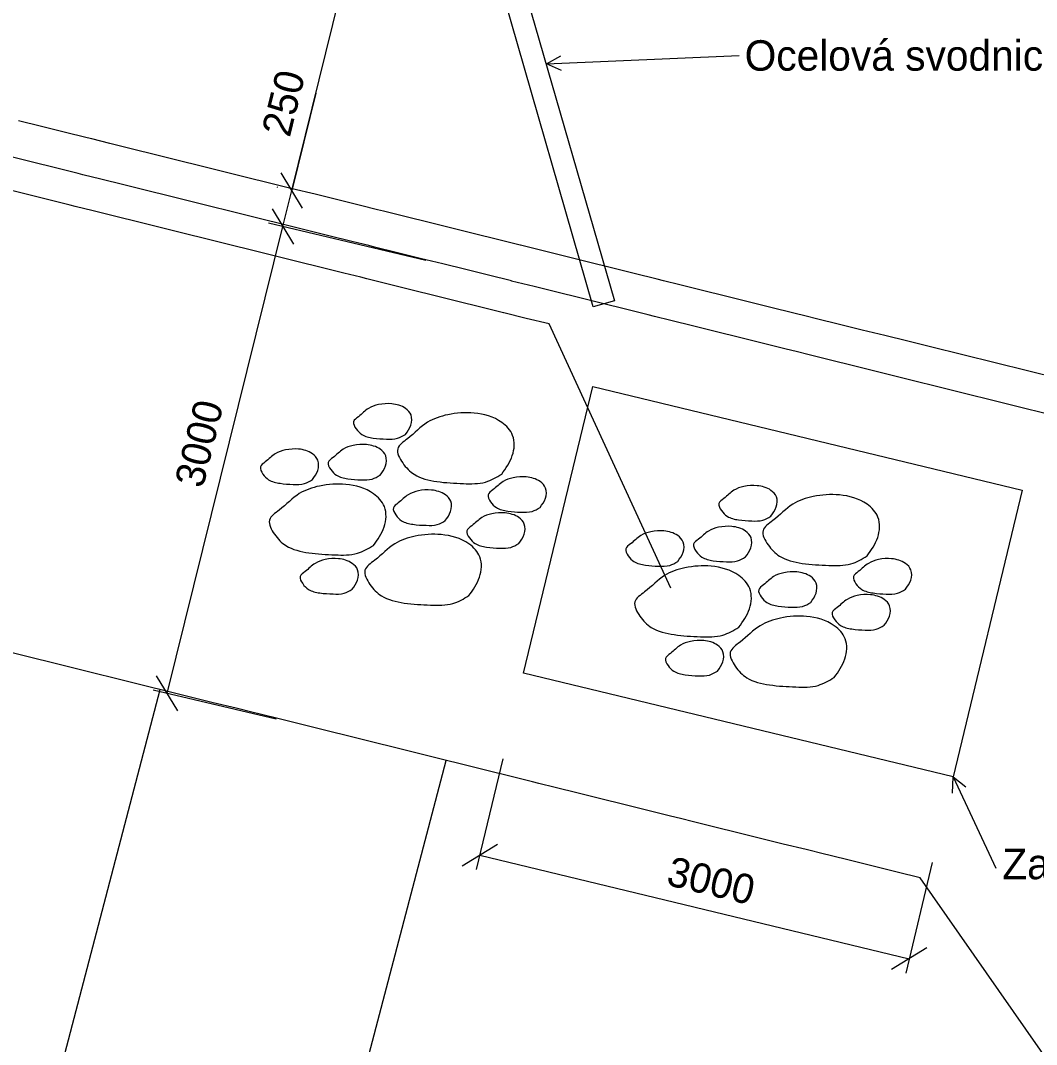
# Model space of a CAD drawing. Extents: x -577013.5 to -576971.5, y -1164310.3 to -1164280.6.
# Drawn here: x -577004.93 to -576998.03, y -1164300.03 to -1164293.08 of the extents above; entities that cross this region are included whole.
import ezdxf

# ---------------------------------------------------------------- set-up
doc = ezdxf.new("R2010")
doc.units = 0
for name, color, linetype in [('V_N1_detaily', 7, 'Continuous'), ('Vrstva 1', 7, 'Continuous'), ('Šrafy', 7, 'Continuous')]:
    doc.layers.add(name, color=color, linetype=linetype)

msp = doc.modelspace()

# ---------------------------------------------------------------- linework, layer by layer
for p, q in [((-577002.7891, -1164288.4094), (-577000.8944, -1164294.9817)), ((-577001.0385, -1164295.0232), (-577002.9332, -1164288.451)), ((-577003.0856, -1164294.2333), (-577001.7682, -1164288.9174)), ((-577002.9216, -1164293.5719), (-577003.0856, -1164294.2333)), ((-577004.7861, -1164293.7991), (-577004.941, -1164293.7607)), ((-577004.6313, -1164293.8375), (-577004.7861, -1164293.7991)), ((-577004.4764, -1164293.8758), (-577004.6313, -1164293.8375)), ((-577004.4445, -1164293.8837), (-577004.4764, -1164293.8758)), ((-577004.3216, -1164293.9142), (-577004.4445, -1164293.8837)), ((-577004.1667, -1164293.9526), (-577004.3216, -1164293.9142)), ((-577004.0118, -1164293.991), (-577004.1667, -1164293.9526)), ((-577003.857, -1164294.0293), (-577004.0118, -1164293.991)), ((-577004.8463, -1164294.0417), (-577005.0011, -1164294.0034)), ((-577004.6914, -1164294.0801), (-577004.8463, -1164294.0417)), ((-577003.7021, -1164294.0677), (-577003.857, -1164294.0293)), ((-577003.5473, -1164294.1061), (-577003.7021, -1164294.0677)), ((-577004.5365, -1164294.1185), (-577004.6914, -1164294.0801)), ((-577004.5046, -1164294.1264), (-577004.5365, -1164294.1185)), ((-577004.3817, -1164294.1569), (-577004.5046, -1164294.1264)), ((-577003.4738, -1164294.1243), (-577003.5473, -1164294.1061)), ((-577003.3924, -1164294.1445), (-577003.4738, -1164294.1243)), ((-577003.013, -1164294.3529), (-577003.1581, -1164294.1137)), ((-577003.013, -1164294.3529), (-577003.1581, -1164294.1137)), ((-577004.2268, -1164294.1952), (-577004.3817, -1164294.1569)), ((-577004.072, -1164294.2336), (-577004.2268, -1164294.1952)), ((-577003.2376, -1164294.1828), (-577003.3924, -1164294.1445)), ((-577003.0827, -1164294.2212), (-577003.2376, -1164294.1828)), ((-577004.8996, -1164294.2571), (-577005.0545, -1164294.2187)), ((-577004.7448, -1164294.2955), (-577004.8996, -1164294.2571)), ((-577003.9171, -1164294.272), (-577004.072, -1164294.2336)), ((-577003.7623, -1164294.3104), (-577003.9171, -1164294.272)), ((-577003.1879, -1164294.209), (-577003.1821, -1164294.2104)), ((-577003.1462, -1164294.4779), (-577003.0856, -1164294.2333)), ((-577002.9279, -1164294.2596), (-577003.0827, -1164294.2212)), ((-577002.773, -1164294.298), (-577002.9279, -1164294.2596)), ((-577004.5899, -1164294.3338), (-577004.7448, -1164294.2955)), ((-577004.558, -1164294.3418), (-577004.5899, -1164294.3338)), ((-577004.4351, -1164294.3722), (-577004.558, -1164294.3418)), ((-577003.6074, -1164294.3487), (-577003.7623, -1164294.3104)), ((-577002.6181, -1164294.3363), (-577002.773, -1164294.298)), ((-577002.5032, -1164294.3648), (-577002.6181, -1164294.3363)), ((-577004.2802, -1164294.4106), (-577004.4351, -1164294.3722)), ((-577004.1253, -1164294.449), (-577004.2802, -1164294.4106)), ((-577003.534, -1164294.3669), (-577003.6074, -1164294.3487)), ((-577003.4526, -1164294.3871), (-577003.534, -1164294.3669)), ((-577003.2977, -1164294.4255), (-577003.4526, -1164294.3871)), ((-577003.2187, -1164294.3583), (-577003.0736, -1164294.5975)), ((-577003.2187, -1164294.3583), (-577003.0736, -1164294.5975)), ((-577002.4633, -1164294.3747), (-577002.5032, -1164294.3648)), ((-577002.3084, -1164294.4131), (-577002.4633, -1164294.3747)), ((-577002.1536, -1164294.4515), (-577002.3084, -1164294.4131)), ((-577003.9705, -1164294.4873), (-577004.1253, -1164294.449)), ((-577003.9316, -1164297.6472), (-577003.1462, -1164294.4779)), ((-577003.1428, -1164294.4639), (-577003.2977, -1164294.4255)), ((-577002.1761, -1164294.7077), (-577003.2427, -1164294.455)), ((-577003.1845, -1164294.6327), (-577003.1462, -1164294.4779)), ((-577002.988, -1164294.5022), (-577003.1428, -1164294.4639)), ((-577001.9987, -1164294.4898), (-577002.1536, -1164294.4515)), ((-577003.8156, -1164294.5257), (-577003.9705, -1164294.4873)), ((-577003.6608, -1164294.5641), (-577003.8156, -1164294.5257)), ((-577002.8331, -1164294.5406), (-577002.988, -1164294.5022)), ((-577002.6783, -1164294.579), (-577002.8331, -1164294.5406)), ((-577001.8439, -1164294.5282), (-577001.9987, -1164294.4898)), ((-577001.689, -1164294.5666), (-577001.8439, -1164294.5282)), ((-577003.5873, -1164294.5823), (-577003.6608, -1164294.5641)), ((-577003.5059, -1164294.6025), (-577003.5873, -1164294.5823)), ((-577003.3511, -1164294.6408), (-577003.5059, -1164294.6025)), ((-577002.5633, -1164294.6075), (-577002.6783, -1164294.579)), ((-577002.5234, -1164294.6174), (-577002.5633, -1164294.6075)), ((-577002.3686, -1164294.6558), (-577002.5234, -1164294.6174)), ((-577001.5342, -1164294.605), (-577001.689, -1164294.5666)), ((-577001.5326, -1164294.6054), (-577001.5342, -1164294.605)), ((-577001.3793, -1164294.6433), (-577001.5326, -1164294.6054)), ((-577003.1962, -1164294.6792), (-577003.3511, -1164294.6408)), ((-577003.0414, -1164294.7176), (-577003.1962, -1164294.6792)), ((-577002.2137, -1164294.6941), (-577002.3686, -1164294.6558)), ((-577002.0589, -1164294.7325), (-577002.2137, -1164294.6941)), ((-577001.2244, -1164294.6817), (-577001.3793, -1164294.6433)), ((-577001.0696, -1164294.7201), (-577001.2244, -1164294.6817)), ((-577002.8865, -1164294.756), (-577003.0414, -1164294.7176)), ((-577002.7316, -1164294.7944), (-577002.8865, -1164294.756)), ((-577001.904, -1164294.7709), (-577002.0589, -1164294.7325)), ((-577000.9147, -1164294.7585), (-577001.0696, -1164294.7201)), ((-577000.7599, -1164294.7968), (-577000.9147, -1164294.7585)), ((-577002.6167, -1164294.8228), (-577002.7316, -1164294.7944)), ((-577002.5768, -1164294.8327), (-577002.6167, -1164294.8228)), ((-577002.4219, -1164294.8711), (-577002.5768, -1164294.8327)), ((-577001.7491, -1164294.8093), (-577001.904, -1164294.7709)), ((-577001.5943, -1164294.8476), (-577001.7491, -1164294.8093)), ((-577000.605, -1164294.8352), (-577000.7599, -1164294.7968)), ((-577002.2671, -1164294.9095), (-577002.4219, -1164294.8711)), ((-577001.5927, -1164294.848), (-577001.5943, -1164294.8476)), ((-577001.4394, -1164294.886), (-577001.5927, -1164294.848)), ((-577001.2846, -1164294.9244), (-577001.4394, -1164294.886)), ((-577000.5619, -1164294.8459), (-577000.605, -1164294.8352)), ((-577000.4502, -1164294.8736), (-577000.5619, -1164294.8459)), ((-577000.2953, -1164294.912), (-577000.4502, -1164294.8736)), ((-577002.1122, -1164294.9479), (-577002.2671, -1164294.9095)), ((-577001.9574, -1164294.9862), (-577002.1122, -1164294.9479)), ((-577001.1297, -1164294.9628), (-577001.2846, -1164294.9244)), ((-577000.9749, -1164295.0011), (-577001.1297, -1164294.9628)), ((-577000.1405, -1164294.9504), (-577000.2953, -1164294.912)), ((-576999.9856, -1164294.9887), (-577000.1405, -1164294.9504)), ((-577001.8025, -1164295.0246), (-577001.9574, -1164294.9862)), ((-577001.6477, -1164295.063), (-577001.8025, -1164295.0246)), ((-577000.8944, -1164294.9817), (-577001.0385, -1164295.0232)), ((-577000.82, -1164295.0395), (-577000.9749, -1164295.0011)), ((-577000.6652, -1164295.0779), (-577000.82, -1164295.0395)), ((-576999.8308, -1164295.0271), (-576999.9856, -1164294.9887)), ((-576999.6759, -1164295.0655), (-576999.8308, -1164295.0271)), ((-577001.6461, -1164295.0634), (-577001.6477, -1164295.063)), ((-577001.4928, -1164295.1014), (-577001.6461, -1164295.0634)), ((-577001.338, -1164295.1397), (-577001.4928, -1164295.1014)), ((-577000.6221, -1164295.0886), (-577000.6652, -1164295.0779)), ((-577000.5103, -1164295.1163), (-577000.6221, -1164295.0886)), ((-576999.5913, -1164295.0864), (-576999.6759, -1164295.0655)), ((-576999.521, -1164295.1039), (-576999.5913, -1164295.0864)), ((-576999.3662, -1164295.1422), (-576999.521, -1164295.1039)), ((-577000.5115, -1164296.9339), (-577001.338, -1164295.1397)), ((-577000.3555, -1164295.1546), (-577000.5103, -1164295.1163)), ((-577000.2006, -1164295.193), (-577000.3555, -1164295.1546)), ((-576999.2113, -1164295.1806), (-576999.3662, -1164295.1422)), ((-576999.0565, -1164295.219), (-576999.2113, -1164295.1806)), ((-577000.0457, -1164295.2314), (-577000.2006, -1164295.193)), ((-576999.8909, -1164295.2698), (-577000.0457, -1164295.2314)), ((-576998.9016, -1164295.2574), (-576999.0565, -1164295.219)), ((-576999.736, -1164295.3081), (-576999.8909, -1164295.2698)), ((-576999.6514, -1164295.3291), (-576999.736, -1164295.3081)), ((-576998.7468, -1164295.2957), (-576998.9016, -1164295.2574)), ((-576996.2548, -1164295.9082), (-576998.7468, -1164295.2957)), ((-576999.5812, -1164295.3465), (-576999.6514, -1164295.3291)), ((-576999.4263, -1164295.3849), (-576999.5812, -1164295.3465)), ((-576999.2715, -1164295.4233), (-576999.4263, -1164295.3849)), ((-576999.1166, -1164295.4616), (-576999.2715, -1164295.4233)), ((-576998.9618, -1164295.5), (-576999.1166, -1164295.4616)), ((-576996.3092, -1164296.1623), (-576998.9618, -1164295.5)), ((-577001.5108, -1164297.5093), (-577001.0418, -1164295.5651)), ((-577001.0418, -1164295.5651), (-576998.1255, -1164296.2686)), ((-576998.1255, -1164296.2686), (-576998.5945, -1164298.2128)), ((-577004.8575, -1164297.4033), (-577005.0123, -1164297.3649)), ((-577004.7026, -1164297.4417), (-577004.8575, -1164297.4033)), ((-577004.5478, -1164297.4801), (-577004.7026, -1164297.4417)), ((-577004.3929, -1164297.5185), (-577004.5478, -1164297.4801)), ((-577004.3195, -1164297.5367), (-577004.3929, -1164297.5185)), ((-577004.2381, -1164297.5568), (-577004.3195, -1164297.5367)), ((-577003.859, -1164297.7668), (-577004.0041, -1164297.5276)), ((-576998.5945, -1164298.2128), (-577001.5108, -1164297.5093)), ((-577004.0832, -1164297.5952), (-577004.2381, -1164297.5568)), ((-577003.9284, -1164297.6336), (-577004.0832, -1164297.5952)), ((-577003.1913, -1164297.8226), (-577004.0281, -1164297.6243)), ((-577003.7735, -1164297.672), (-577003.9284, -1164297.6336)), ((-577003.6186, -1164297.7103), (-577003.7735, -1164297.672)), ((-577003.4638, -1164297.7487), (-577003.6186, -1164297.7103)), ((-577003.3488, -1164297.7772), (-577003.4638, -1164297.7487)), ((-577003.3089, -1164297.7871), (-577003.3488, -1164297.7772)), ((-577003.1541, -1164297.8255), (-577003.3089, -1164297.7871)), ((-577002.9992, -1164297.8638), (-577003.1541, -1164297.8255)), ((-577002.8444, -1164297.9022), (-577002.9992, -1164297.8638)), ((-577002.6895, -1164297.9406), (-577002.8444, -1164297.9022)), ((-577002.5347, -1164297.979), (-577002.6895, -1164297.9406)), ((-577002.3798, -1164298.0173), (-577002.5347, -1164297.979)), ((-577002.3782, -1164298.0177), (-577002.3798, -1164298.0173)), ((-577002.2249, -1164298.0557), (-577002.3782, -1164298.0177)), ((-577002.0701, -1164298.0941), (-577002.2249, -1164298.0557)), ((-577001.9152, -1164298.1325), (-577002.0701, -1164298.0941)), ((-577001.6515, -1164298.0926), (-577001.8323, -1164298.842)), ((-577001.7604, -1164298.1708), (-577001.9152, -1164298.1325)), ((-577001.6055, -1164298.2092), (-577001.7604, -1164298.1708)), ((-577001.4507, -1164298.2476), (-577001.6055, -1164298.2092)), ((-577001.4076, -1164298.2583), (-577001.4507, -1164298.2476)), ((-577001.2958, -1164298.286), (-577001.4076, -1164298.2583)), ((-577001.141, -1164298.3243), (-577001.2958, -1164298.286)), ((-577000.9861, -1164298.3627), (-577001.141, -1164298.3243)), ((-577000.8312, -1164298.4011), (-577000.9861, -1164298.3627)), ((-577000.6764, -1164298.4395), (-577000.8312, -1164298.4011)), ((-577000.5215, -1164298.4778), (-577000.6764, -1164298.4395)), ((-577000.4369, -1164298.4988), (-577000.5215, -1164298.4778)), ((-577000.3667, -1164298.5162), (-577000.4369, -1164298.4988)), ((-577000.2118, -1164298.5546), (-577000.3667, -1164298.5162)), ((-577000.057, -1164298.593), (-577000.2118, -1164298.5546)), ((-576999.9021, -1164298.6314), (-577000.057, -1164298.593)), ((-576999.7473, -1164298.6697), (-576999.9021, -1164298.6314)), ((-577001.9295, -1164298.8185), (-577001.6882, -1164298.671)), ((-576999.5924, -1164298.7081), (-576999.7473, -1164298.6697)), ((-576999.4663, -1164298.7394), (-576999.5924, -1164298.7081)), ((-577001.8089, -1164298.7447), (-576998.8925, -1164299.4483)), ((-576999.4376, -1164298.7465), (-576999.4663, -1164298.7394)), ((-576999.2827, -1164298.7849), (-576999.4376, -1164298.7465)), ((-576999.1278, -1164298.8232), (-576999.2827, -1164298.7849)), ((-576998.973, -1164298.8616), (-576999.1278, -1164298.8232)), ((-576998.8181, -1164298.9), (-576998.973, -1164298.8616)), ((-576998.7352, -1164298.7961), (-576998.916, -1164299.5455)), ((-576996.082, -1164302.8053), (-576998.8181, -1164298.9)), ((-576998.7719, -1164299.3745), (-576999.0132, -1164299.522))]:
    msp.add_line(p, q)
at = {"layer": 'V_N1_detaily'}
for points in [[(-577002.313, -1164295.8889), (-577002.3676, -1164295.9157), (-577002.4429, -1164295.9211), (-577002.533, -1164295.914), (-577002.6101, -1164295.8897), (-577002.6491, -1164295.8509), (-577002.666, -1164295.803), (-577002.633, -1164295.7689), (-577002.5648, -1164295.7131), (-577002.496, -1164295.6873), (-577002.4068, -1164295.6818), (-577002.3127, -1164295.7134), (-577002.2759, -1164295.7574), (-577002.2768, -1164295.8262), (-577002.313, -1164295.8889)], [(-577001.6601, -1164296.1587), (-577001.7694, -1164296.2124), (-577001.9199, -1164296.2231), (-577002.1001, -1164296.209), (-577002.2543, -1164296.1603), (-577002.3323, -1164296.0828), (-577002.3662, -1164295.987), (-577002.3001, -1164295.9189), (-577002.1638, -1164295.8072), (-577002.0261, -1164295.7556), (-577001.8477, -1164295.7446), (-577001.6595, -1164295.8078), (-577001.5859, -1164295.8958), (-577001.5877, -1164296.0333), (-577001.6601, -1164296.1587)], [(-577002.9457, -1164296.1962), (-577003.0003, -1164296.223), (-577003.0756, -1164296.2284), (-577003.1657, -1164296.2213), (-577003.2428, -1164296.197), (-577003.2818, -1164296.1582), (-577003.2987, -1164296.1103), (-577003.2657, -1164296.0762), (-577003.1975, -1164296.0204), (-577003.1287, -1164295.9946), (-577003.0395, -1164295.9891), (-577002.9454, -1164296.0207), (-577002.9086, -1164296.0647), (-577002.9095, -1164296.1334), (-577002.9457, -1164296.1962)], [(-577002.4851, -1164296.1657), (-577002.5398, -1164296.1925), (-577002.615, -1164296.1979), (-577002.7051, -1164296.1908), (-577002.7822, -1164296.1665), (-577002.8212, -1164296.1277), (-577002.8382, -1164296.0798), (-577002.8051, -1164296.0457), (-577002.737, -1164295.9899), (-577002.6681, -1164295.9641), (-577002.5789, -1164295.9586), (-577002.4848, -1164295.9902), (-577002.448, -1164296.0342), (-577002.4489, -1164296.103), (-577002.4851, -1164296.1657)], [(-577002.5309, -1164296.6428), (-577002.6402, -1164296.6964), (-577002.7908, -1164296.7072), (-577002.9709, -1164296.6931), (-577003.1251, -1164296.6444), (-577003.2031, -1164296.5668), (-577003.237, -1164296.471), (-577003.1709, -1164296.4029), (-577003.0346, -1164296.2913), (-577002.8969, -1164296.2397), (-577002.7185, -1164296.2287), (-577002.5304, -1164296.2919), (-577002.4567, -1164296.3798), (-577002.4585, -1164296.5174), (-577002.5309, -1164296.6428)], [(-577001.3991, -1164296.385), (-577001.4537, -1164296.4118), (-577001.529, -1164296.4172), (-577001.6191, -1164296.4101), (-577001.6962, -1164296.3858), (-577001.7352, -1164296.347), (-577001.7521, -1164296.2991), (-577001.7191, -1164296.265), (-577001.6509, -1164296.2092), (-577001.5821, -1164296.1834), (-577001.4929, -1164296.1779), (-577001.3988, -1164296.2095), (-577001.362, -1164296.2535), (-577001.3629, -1164296.3223), (-577001.3991, -1164296.385)], [(-577002.0428, -1164296.4743), (-577002.0974, -1164296.5011), (-577002.1727, -1164296.5065), (-577002.2628, -1164296.4995), (-577002.3399, -1164296.4751), (-577002.3789, -1164296.4363), (-577002.3958, -1164296.3884), (-577002.3628, -1164296.3544), (-577002.2946, -1164296.2986), (-577002.2258, -1164296.2728), (-577002.1366, -1164296.2673), (-577002.0425, -1164296.2989), (-577002.0057, -1164296.3428), (-577002.0066, -1164296.4116), (-577002.0428, -1164296.4743)], [(-576999.8314, -1164296.4444), (-576999.8861, -1164296.4712), (-576999.9614, -1164296.4766), (-577000.0515, -1164296.4696), (-577000.1286, -1164296.4452), (-577000.1676, -1164296.4065), (-577000.1845, -1164296.3585), (-577000.1514, -1164296.3245), (-577000.0833, -1164296.2687), (-577000.0144, -1164296.2429), (-576999.9253, -1164296.2374), (-576999.8312, -1164296.269), (-576999.7944, -1164296.313), (-576999.7953, -1164296.3817), (-576999.8314, -1164296.4444)], [(-576999.1785, -1164296.7143), (-576999.2879, -1164296.7679), (-576999.4384, -1164296.7787), (-576999.6186, -1164296.7646), (-576999.7728, -1164296.7159), (-576999.8508, -1164296.6383), (-576999.8847, -1164296.5425), (-576999.8185, -1164296.4744), (-576999.6823, -1164296.3628), (-576999.5445, -1164296.3111), (-576999.3662, -1164296.3002), (-576999.178, -1164296.3634), (-576999.1043, -1164296.4513), (-576999.1062, -1164296.5889), (-576999.1785, -1164296.7143)], [(-577001.5434, -1164296.6293), (-577001.598, -1164296.6561), (-577001.6733, -1164296.6615), (-577001.7634, -1164296.6544), (-577001.8405, -1164296.6301), (-577001.8795, -1164296.5913), (-577001.8964, -1164296.5434), (-577001.8634, -1164296.5094), (-577001.7952, -1164296.4535), (-577001.7264, -1164296.4277), (-577001.6372, -1164296.4223), (-577001.5431, -1164296.4539), (-577001.5063, -1164296.4978), (-577001.5072, -1164296.5666), (-577001.5434, -1164296.6293)], [(-577001.8826, -1164296.9835), (-577001.9919, -1164297.0372), (-577002.1425, -1164297.0479), (-577002.3227, -1164297.0338), (-577002.4769, -1164296.9851), (-577002.5548, -1164296.9076), (-577002.5887, -1164296.8117), (-577002.5226, -1164296.7437), (-577002.3863, -1164296.632), (-577002.2486, -1164296.5804), (-577002.0702, -1164296.5694), (-577001.8821, -1164296.6326), (-577001.8084, -1164296.7206), (-577001.8103, -1164296.8581), (-577001.8826, -1164296.9835)], [(-577000.4641, -1164296.7517), (-577000.5188, -1164296.7785), (-577000.5941, -1164296.7839), (-577000.6842, -1164296.7768), (-577000.7613, -1164296.7525), (-577000.8003, -1164296.7137), (-577000.8172, -1164296.6658), (-577000.7841, -1164296.6318), (-577000.716, -1164296.5759), (-577000.6471, -1164296.5501), (-577000.5579, -1164296.5447), (-577000.4639, -1164296.5763), (-577000.427, -1164296.6202), (-577000.428, -1164296.689), (-577000.4641, -1164296.7517)], [(-577000.0036, -1164296.7212), (-577000.0583, -1164296.748), (-577000.1335, -1164296.7534), (-577000.2236, -1164296.7464), (-577000.3007, -1164296.722), (-577000.3397, -1164296.6832), (-577000.3567, -1164296.6353), (-577000.3236, -1164296.6013), (-577000.2555, -1164296.5455), (-577000.1866, -1164296.5196), (-577000.0974, -1164296.5142), (-577000.0033, -1164296.5458), (-576999.9665, -1164296.5897), (-576999.9674, -1164296.6585), (-577000.0036, -1164296.7212)], [(-577002.6756, -1164296.9403), (-577002.7302, -1164296.9671), (-577002.8055, -1164296.9725), (-577002.8956, -1164296.9654), (-577002.9727, -1164296.9411), (-577003.0117, -1164296.9023), (-577003.0286, -1164296.8544), (-577002.9956, -1164296.8203), (-577002.9274, -1164296.7645), (-577002.8586, -1164296.7387), (-577002.7694, -1164296.7332), (-577002.6753, -1164296.7648), (-577002.6385, -1164296.8088), (-577002.6394, -1164296.8776), (-577002.6756, -1164296.9403)], [(-577000.0494, -1164297.1983), (-577000.1587, -1164297.252), (-577000.3093, -1164297.2628), (-577000.4894, -1164297.2486), (-577000.6436, -1164297.1999), (-577000.7216, -1164297.1224), (-577000.7555, -1164297.0266), (-577000.6894, -1164296.9585), (-577000.5531, -1164296.8468), (-577000.4154, -1164296.7952), (-577000.237, -1164296.7842), (-577000.0489, -1164296.8474), (-576999.9752, -1164296.9354), (-576999.977, -1164297.0729), (-577000.0494, -1164297.1983)], [(-576998.9176, -1164296.9405), (-576998.9722, -1164296.9673), (-576999.0475, -1164296.9727), (-576999.1376, -1164296.9656), (-576999.2147, -1164296.9413), (-576999.2537, -1164296.9025), (-576999.2706, -1164296.8546), (-576999.2376, -1164296.8206), (-576999.1694, -1164296.7648), (-576999.1006, -1164296.7389), (-576999.0114, -1164296.7335), (-576998.9173, -1164296.7651), (-576998.8805, -1164296.809), (-576998.8814, -1164296.8778), (-576998.9176, -1164296.9405)], [(-576999.5612, -1164297.0299), (-576999.6159, -1164297.0567), (-576999.6912, -1164297.0621), (-576999.7813, -1164297.055), (-576999.8584, -1164297.0307), (-576999.8974, -1164296.9919), (-576999.9143, -1164296.944), (-576999.8812, -1164296.9099), (-576999.8131, -1164296.8541), (-576999.7442, -1164296.8283), (-576999.6551, -1164296.8228), (-576999.561, -1164296.8544), (-576999.5242, -1164296.8984), (-576999.5251, -1164296.9672), (-576999.5612, -1164297.0299)], [(-576999.0619, -1164297.1849), (-576999.1165, -1164297.2117), (-576999.1918, -1164297.2171), (-576999.2819, -1164297.21), (-576999.359, -1164297.1856), (-576999.398, -1164297.1469), (-576999.4149, -1164297.099), (-576999.3819, -1164297.0649), (-576999.3137, -1164297.0091), (-576999.2449, -1164296.9833), (-576999.1557, -1164296.9778), (-576999.0616, -1164297.0094), (-576999.0248, -1164297.0534), (-576999.0257, -1164297.1221), (-576999.0619, -1164297.1849)], [(-576999.4011, -1164297.5391), (-576999.5104, -1164297.5927), (-576999.661, -1164297.6035), (-576999.8411, -1164297.5894), (-576999.9953, -1164297.5407), (-577000.0733, -1164297.4631), (-577000.1072, -1164297.3673), (-577000.0411, -1164297.2992), (-576999.9048, -1164297.1876), (-576999.7671, -1164297.1359), (-576999.5887, -1164297.125), (-576999.4006, -1164297.1882), (-576999.3269, -1164297.2761), (-576999.3287, -1164297.4137), (-576999.4011, -1164297.5391)], [(-577000.194, -1164297.4958), (-577000.2487, -1164297.5226), (-577000.324, -1164297.528), (-577000.4141, -1164297.521), (-577000.4912, -1164297.4966), (-577000.5302, -1164297.4578), (-577000.5471, -1164297.4099), (-577000.514, -1164297.3759), (-577000.4459, -1164297.3201), (-577000.377, -1164297.2943), (-577000.2879, -1164297.2888), (-577000.1938, -1164297.3204), (-577000.1569, -1164297.3643), (-577000.1579, -1164297.4331), (-577000.194, -1164297.4958)]]:
    msp.add_spline(points, degree=3, dxfattribs=at)
at = {"layer": 'Vrstva 1'}
for p, q in [((-577001.356, -1164293.3738), (-577000.0461, -1164293.317)), ((-576998.5945, -1164298.2128), (-576998.3047, -1164298.8338))]:
    msp.add_line(p, q, dxfattribs=at)
for points in [[(-577001.2539, -1164293.4195), (-577001.356, -1164293.3738), (-577001.2583, -1164293.3196)], [(-576998.5975, -1164298.3246), (-576998.5945, -1164298.2128), (-576998.5069, -1164298.2823)]]:
    msp.add_lwpolyline(points, dxfattribs=at)
at = {"layer": 'Šrafy'}
for p, q in [((-577004.9217, -1164301.2156), (-577003.9794, -1164297.6209)), ((-577002.987, -1164301.7227), (-577002.038, -1164298.102))]:
    msp.add_line(p, q, dxfattribs=at)

# ---------------------------------------------------------------- texts
for s, height, rotation, p in [('250', 0.19841, 76.08153, (-577003.0999, -1164293.8786)), ('3000', 0.19841, 76.08153, (-577003.6902, -1164296.2608)), ('3000', 0.2, 346.43707, (-577000.5495, -1164298.9457))]:
    msp.add_text(s, height=height, rotation=rotation).set_placement(p)
at = {"layer": 'Vrstva 1'}
for s, p in [('Ocelová svodnice dl. 7m', (-577000.0097, -1164293.4203)), ('Zasakovací jímka', (-576998.26, -1164298.9087))]:
    msp.add_text(s, height=0.206627, dxfattribs=at).set_placement(p)

doc.saveas('drawing.dxf')
